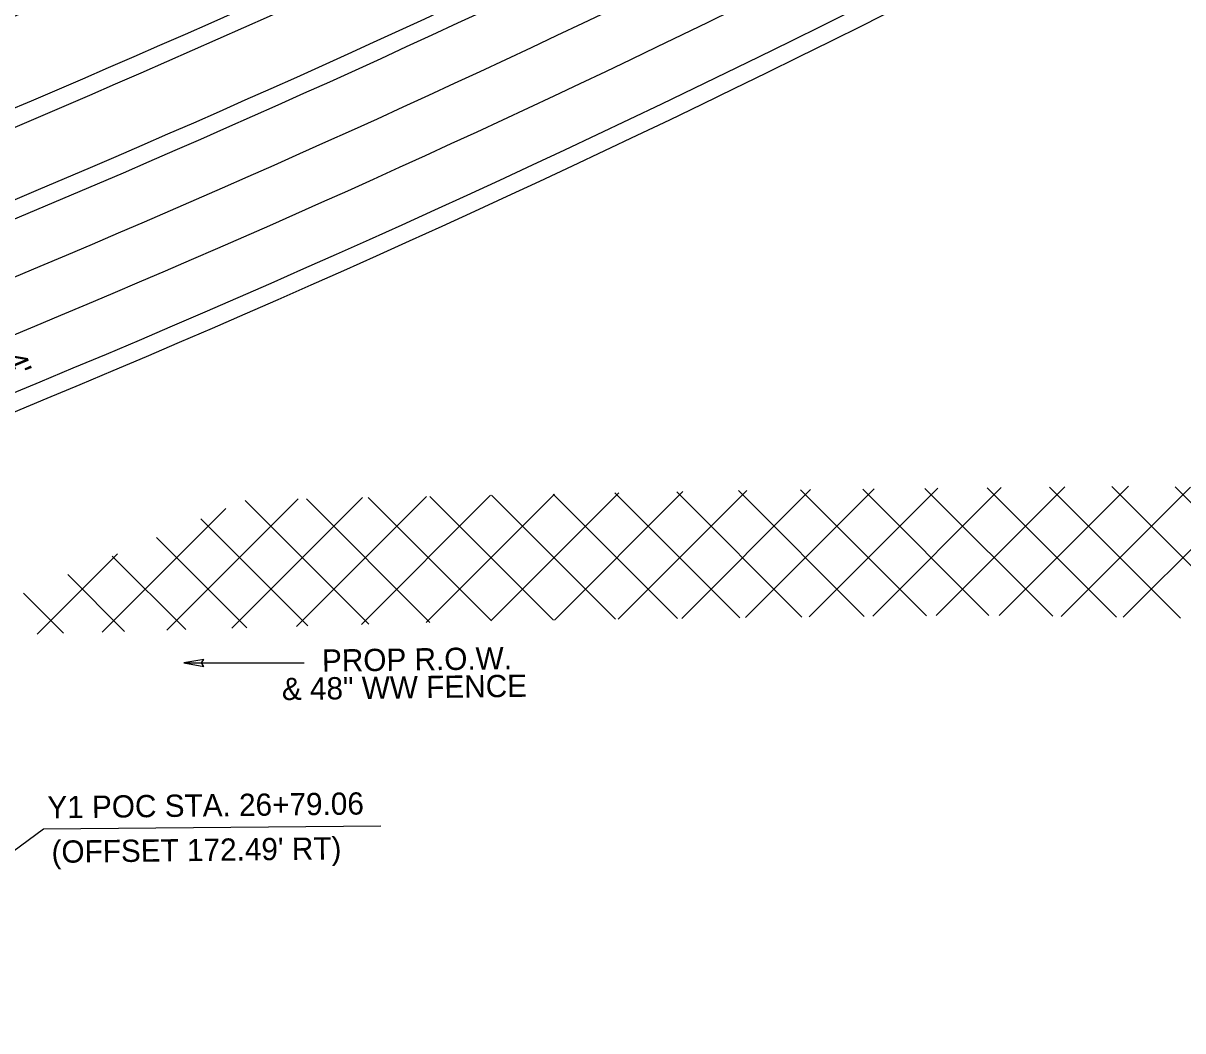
# Model space of a CAD drawing. Extents: x 2389099 to 2405615, y 552200 to 573532.
# Drawn here: x 2391469.5 to 2391730.2, y 552596.7 to 552823.2 of the extents above; entities that cross this region are included whole.
import ezdxf

# ---------------------------------------------------------------- set-up
doc = ezdxf.new("R2010")
doc.units = 0
for name, color, linetype in [('Old_Level_11', 7, 'Continuous'), ('Prop Cable Guiderail Double Face', 7, 'Continuous'), ('Prop Dimension', 7, 'Continuous'), ('Prop Dimension Text', 7, 'Continuous'), ('Prop DSN Text', 7, 'Continuous'), ('Prop EOT', 7, 'Continuous'), ('Prop Hatching', 7, 'Continuous'), ('Prop Horizontal Alignment', 7, 'Continuous'), ('Prop Lane Lines', 7, 'Continuous')]:
    doc.layers.add(name, color=color, linetype=linetype)

msp = doc.modelspace()

# ---------------------------------------------------------------- linework, layer by layer
at = {"layer": 'Prop Cable Guiderail Double Face'}
msp.add_arc((2390350.01, 555442.22), 2869, 286.11768, 302.22693, dxfattribs=at)
at = {"layer": 'Prop Dimension'}
for p, q in [((2391473.99, 552642.02), (2391412.75, 552596.71)), ((2391549.86, 552642.67), (2391473.99, 552642.02))]:
    msp.add_line(p, q, dxfattribs=at)
at = {"layer": 'Prop DSN Text'}
msp.add_line((2391505.59, 552679.39), (2391532.6, 552679.39), dxfattribs=at)
msp.add_lwpolyline([(2391510.09, 552680.16), (2391505.59, 552679.39), (2391510.11, 552678.59), (2391509.54, 552679.39)], close=True, dxfattribs=at)
at = {"layer": 'Prop EOT'}
for radius, start, end in [(2842, 286.11768, 302.22693), (2846, 286.11763, 302.22693), (2884, 286.11768, 302.22693), (2888, 286.11768, 302.22693), (2924, 292.11719, 302.22692), (2928, 292.11719, 302.22692)]:
    msp.add_arc((2390350.01, 555442.22), radius, start, end, dxfattribs=at)
at = {"layer": 'Prop Hatching'}
for p, q in [((2391646.18, 552689.73), (2391675.1, 552718.65)), ((2391660.48, 552689.88), (2391689.39, 552718.8)), ((2391700.97, 552689.88), (2391672.24, 552718.62)), ((2391674.77, 552690.04), (2391703.69, 552718.95)), ((2391715.32, 552689.68), (2391686.23, 552718.77)), ((2391688.93, 552690.06), (2391717.98, 552719.1)), ((2391729.67, 552689.47), (2391700.23, 552718.91)), ((2391702.88, 552689.86), (2391731.92, 552718.9)), ((2391744.02, 552689.27), (2391714.22, 552719.06)), ((2391716.82, 552689.66), (2391745.83, 552718.67)), ((2391758.36, 552689.06), (2391728.46, 552718.96)), ((2391501.79, 552686.76), (2391531.3, 552716.27)), ((2391516.36, 552687.19), (2391545.72, 552716.55)), ((2391530.94, 552687.62), (2391560.13, 552716.82)), ((2391560.92, 552688.52), (2391533.13, 552716.31)), ((2391545.51, 552688.06), (2391574.55, 552717.09)), ((2391574.73, 552688.85), (2391547.01, 552716.57)), ((2391560.09, 552688.49), (2391588.96, 552717.36)), ((2391588.69, 552689.03), (2391560.89, 552716.83)), ((2391574.59, 552688.85), (2391603.38, 552717.64)), ((2391602.64, 552689.22), (2391574.77, 552717.1)), ((2391616.6, 552689.4), (2391588.65, 552717.36)), ((2391588.92, 552689.04), (2391617.79, 552717.91)), ((2391630.58, 552689.56), (2391602.53, 552717.62)), ((2391603.25, 552689.23), (2391632.2, 552718.18)), ((2391644.58, 552689.71), (2391616.41, 552717.88)), ((2391617.58, 552689.42), (2391646.51, 552718.35)), ((2391658.57, 552689.86), (2391630.29, 552718.14)), ((2391631.88, 552689.58), (2391660.81, 552718.5)), ((2391672.56, 552690.01), (2391644.25, 552718.32)), ((2391686.62, 552690.09), (2391658.24, 552718.47)), ((2391487.21, 552686.32), (2391514.99, 552714.11)), ((2391547.19, 552688.11), (2391519.36, 552715.93)), ((2391533.45, 552687.7), (2391509.39, 552711.76)), ((2391519.72, 552687.29), (2391499.42, 552707.59)), ((2391472.63, 552685.89), (2391490.68, 552703.93)), ((2391505.99, 552686.88), (2391489.45, 552703.42)), ((2391492.25, 552686.47), (2391479.48, 552699.25)), ((2391478.52, 552686.06), (2391469.51, 552695.07))]:
    msp.add_line(p, q, dxfattribs=at)
at = {"layer": 'Prop Horizontal Alignment'}
msp.add_arc((2390350.01, 555442.22), 2865, 286.11768, 302.22693, dxfattribs=at)
at = {"layer": 'Prop Lane Lines'}
for radius, start, end in [(2818, 290.89849, 302.22692), (2830, 286.11768, 302.22693), (2900, 286.11768, 302.22693), (2912, 286.11768, 302.22693)]:
    msp.add_arc((2390350.01, 555442.22), radius, start, end, dxfattribs=at)

# ---------------------------------------------------------------- texts
at = {"layer": 'Old_Level_11'}
for s, p in [('Y1 POC STA. 26+79.06', (2391474.92, 552644.44)), ("(OFFSET 172.49' RT)", (2391475.86, 552634.45))]:
    msp.add_text(s, height=5, rotation=0.7142, dxfattribs=at).set_placement(p)
at = {"layer": 'Prop Dimension Text'}
msp.add_text("4'", height=5, rotation=292.1169, dxfattribs=at).set_placement((2391465.02, 552748.13))
at = {"layer": 'Prop DSN Text'}
for s, p in [('PROP R.O.W.', (2391536.68, 552677.41)), ('& 48" WW FENCE', (2391527.65, 552671.04))]:
    msp.add_text(s, height=5, rotation=0.7827, dxfattribs=at).set_placement(p)

doc.saveas('drawing.dxf')
